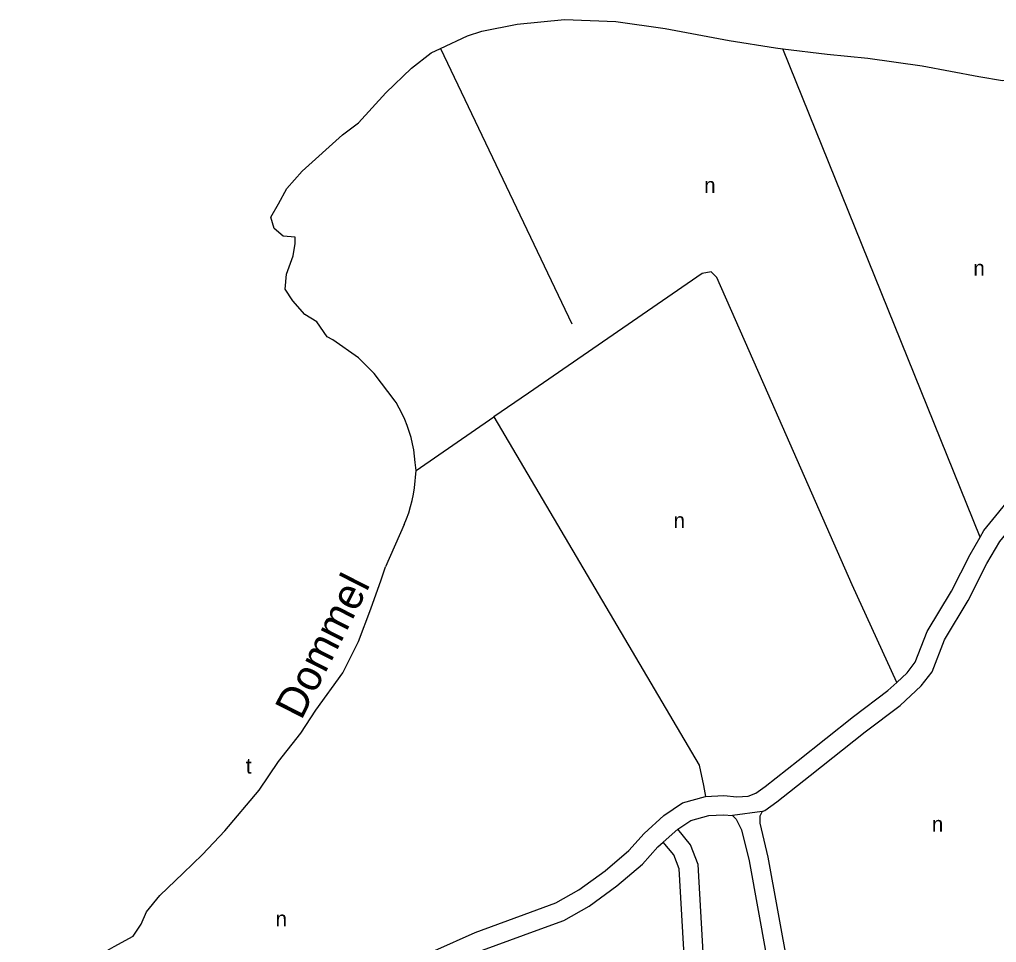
# Model space of a CAD drawing. Extents: x 162427 to 165104, y 384242 to 386287.
# Drawn here: x 163398.1 to 163652, y 386023.9 to 386263.7 of the extents above; entities that cross this region are included whole.
import ezdxf

# ---------------------------------------------------------------- set-up
doc = ezdxf.new("R2010")
doc.units = 0
for name, color, linetype in [('BLT_Basislijn', 7, 'Continuous'), ('BLT_Centroide', 7, 'Continuous'), ('BLT_Vlakafsluiter', 7, 'Continuous'), ('BLT_Waternaam_spoorwegen', 7, 'Continuous')]:
    doc.layers.add(name, color=color, linetype=linetype)

msp = doc.modelspace()

# ---------------------------------------------------------------- linework, layer by layer
at = {"layer": 'BLT_Basislijn'}
for p, q in [((163507.54, 386256.19), (163541.66, 386184.66)), ((163647.78, 386129.21), (163596.49, 386256.13)), ((163501.23, 386146.57), (163521.4, 386160.45)), ((163498.09, 386132.48), (163493.28, 386121.46))]:
    msp.add_line(p, q, dxfattribs=at)
for points in [[(163507.54, 386256.19), (163514.56, 386259.49), (163518.32, 386260.74), (163527.5, 386262.5), (163539.8, 386263.72), (163553.08, 386263.24), (163565.94, 386261.37), (163582.6, 386258.24), (163594.64, 386256.36), (163596.49, 386256.13)], [(163495.76, 386164.55), (163490.28, 386171.77), (163486.22, 386175.84), (163479.56, 386180.53), (163478.12, 386181.29), (163475.36, 386185.18), (163472.27, 386187.1), (163469.2, 386190.65), (163467.16, 386193.65), (163467.49, 386197.59), (163469.29, 386202.35), (163469.79, 386205.52), (163469.76, 386207.18), (163466.62, 386207.41), (163464.29, 386209.45), (163463.41, 386212.37), (163465.45, 386215.86), (163467.59, 386219.78), (163471.62, 386224.36), (163482.03, 386233.74), (163486.25, 386236.88), (163493.34, 386244.66), (163500, 386251.12), (163505.13, 386255.07), (163507.54, 386256.19)], [(163596.49, 386256.13), (163608.09, 386254.69), (163618.63, 386253.72), (163632.78, 386251.73), (163647.46, 386248.94)], [(163647.46, 386248.94), (163653.62, 386247.88), (163656.76, 386248.16)], [(163626.13, 386091.46), (163614.58, 386116.85), (163592.62, 386166.67), (163579.4, 386196.66), (163577.88, 386198.12), (163575.52, 386197.77), (163530.42, 386166.67), (163521.4, 386160.45)], [(163501.23, 386146.57), (163500.96, 386148.59), (163500.81, 386150.24), (163500.58, 386151.87), (163500.27, 386153.49), (163499.89, 386155.1), (163499.42, 386156.69), (163498.88, 386158.25), (163498.27, 386159.78), (163497.58, 386161.28), (163496.82, 386162.75), (163495.99, 386164.18), (163495.76, 386164.55)], [(163521.4, 386160.45), (163574.76, 386069.99), (163575.86, 386064.64), (163576.43, 386061.82)], [(163647.78, 386129.21), (163648.76, 386130.92), (163656.88, 386140.86), (163662.63, 386146.34), (163666.26, 386148.77), (163671.5, 386150.94), (163678.54, 386152.18), (163692.23, 386153.55)], [(163498.09, 386132.48), (163498.73, 386134.01), (163499.29, 386135.56), (163499.77, 386137.14), (163500.18, 386138.74), (163500.5, 386140.36), (163500.75, 386141.99), (163501.23, 386146.57)], [(163591.13, 386057.93), (163591.84, 386058.18), (163594.95, 386060.42), (163603.6, 386067.29), (163617.91, 386078.66), (163627.03, 386085.49), (163632.51, 386090.55), (163635.33, 386094.23), (163638.53, 386102.5), (163644.71, 386112.74), (163649.59, 386122.36), (163652.89, 386128.07), (163660.55, 386137.46), (163665.77, 386142.42), (163666.58, 386142.96)], [(163626.13, 386091.46), (163628.8, 386093.93), (163630.93, 386096.7), (163634.02, 386104.71), (163640.33, 386115.16), (163645.19, 386124.74), (163647.78, 386129.21)], [(163398.13, 386004.98), (163406.08, 386011.25), (163414.03, 386017.52), (163417.86, 386020.06), (163422.76, 386022.79), (163427.65, 386025.51), (163429.77, 386028.61), (163431.15, 386031.88), (163434.62, 386036.12), (163440.64, 386041.91), (163445.66, 386046.76), (163451.51, 386052.88), (163460.41, 386063.45), (163465.42, 386070.9), (163471.22, 386078.3), (163475.18, 386084.26), (163482.17, 386093.95), (163486.23, 386102.07), (163489.46, 386110.59), (163492.08, 386118.14), (163493.28, 386121.46)], [(163576.43, 386061.82), (163581.22, 386062.07), (163584.6, 386061.75), (163587.47, 386061.94), (163589.5, 386062.65), (163591.94, 386064.41), (163600.49, 386071.21), (163614.85, 386082.62), (163623.83, 386089.34), (163626.13, 386091.46)], [(163506.07, 386021.78), (163516.55, 386026.47), (163530.98, 386031.77), (163537.52, 386034.18), (163543.47, 386037.55), (163550.31, 386042.51), (163556.51, 386047.79), (163560.49, 386052.22), (163565.62, 386056.91), (163570.48, 386060.14), (163576.43, 386061.82)], [(163591.13, 386057.93), (163590.52, 386056.72), (163590.52, 386054.91), (163592.63, 386046.09), (163608.57, 385958.62), (163609.34, 385955.39), (163609.46, 385955.12), (163610.17, 385955.11), (163612.71, 385955.57), (163630.43, 385960.08), (163656.77, 385967.2)], [(163569.2, 386053.29), (163572.6, 386055.54), (163577.25, 386056.86), (163581.11, 386057.06), (163583.42, 386056.84)], [(163583.42, 386056.84), (163584.42, 386055.9), (163585.81, 386053.13), (163587.74, 386045.06), (163603.67, 385957.59), (163604.59, 385953.77), (163605.29, 385952.21), (163606.79, 385950.63), (163608.59, 385950.14)], [(163581.88, 385866.37), (163583.41, 385869.1), (163586.99, 385875.51), (163587.87, 385879.64), (163587.34, 385894.01), (163582.9, 385947.01), (163576.96, 386001.42), (163574.54, 386044.1), (163572.54, 386049.22), (163569.2, 386053.29)], [(163513.68, 386019.71), (163518.44, 386021.84), (163532.7, 386027.08), (163539.63, 386029.62), (163546.17, 386033.33), (163553.41, 386038.57), (163560.01, 386044.2), (163564.04, 386048.7), (163565.44, 386049.98)], [(163577.12, 385868.1), (163579.05, 385871.55), (163582.26, 385877.29), (163582.85, 385880.07), (163582.35, 385893.71), (163577.92, 385946.53), (163571.98, 386001.01), (163569.59, 386043.03), (163568.17, 386046.66), (163565.44, 386049.98)]]:
    msp.add_lwpolyline(points, dxfattribs=at)
at = {"layer": 'BLT_Vlakafsluiter'}
for p, q in [((163591.13, 386057.93), (163583.42, 386056.84)), ((163565.44, 386049.98), (163569.2, 386053.29))]:
    msp.add_line(p, q, dxfattribs=at)

# ---------------------------------------------------------------- texts
at = {"layer": 'BLT_Centroide'}
for s, p in [('n', (163576.07, 386218.67)), ('n', (163646.04, 386197.15)), ('n', (163568.12, 386131.56)), ('t', (163456.95, 386067.77)), ('n', (163635.26, 386052.64)), ('n', (163464.67, 386028.05))]:
    msp.add_text(s, height=4, dxfattribs=at).set_placement(p)
at = {"layer": 'BLT_Waternaam_spoorwegen'}
msp.add_text('Dommel', height=8, rotation=63.0412, dxfattribs=at).set_placement((163471.36, 386081.45))

doc.saveas('drawing.dxf')
